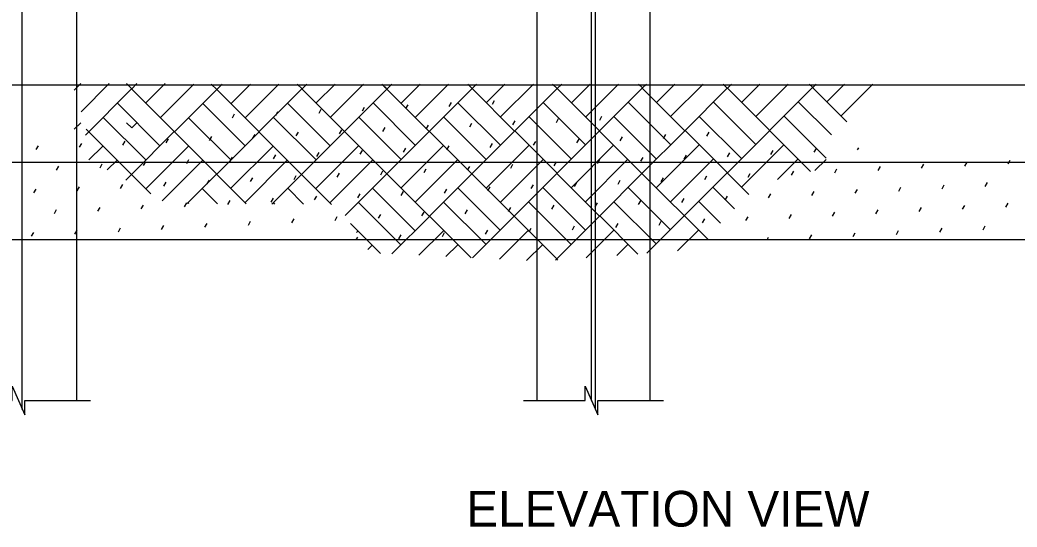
# Model space of a CAD drawing. Extents: x 0 to 61.6, y 0 to 38.9.
# Drawn here: x 19.47 to 30.2, y 12.86 to 18.31 of the extents above; entities that cross this region are included whole.
import ezdxf

# ---------------------------------------------------------------- set-up
doc = ezdxf.new("R2010")
doc.units = 0
for name, color, linetype in [('Dimension', 7, 'Continuous'), ('GroundLines', 7, 'Continuous'), ('Patterning', 7, 'Continuous'), ('SteelMisc', 7, 'Continuous'), ('SteelMisc_h', 7, 'Continuous'), ('Symbols', 7, 'Continuous'), ('TextStructures', 7, 'Continuous'), ('Wood_h', 7, 'Continuous')]:
    doc.layers.add(name, color=color, linetype=linetype)

msp = doc.modelspace()

# ---------------------------------------------------------------- linework, layer by layer
at = {"layer": 'Dimension'}
for p, q in [((23.4, 17.579), (23.409, 17.594)), ((23.621, 17.358), (23.646, 17.4)), ((24.088, 17.382), (24.112, 17.424)), ((24.554, 17.406), (24.576, 17.444)), ((21.756, 17.26), (21.78, 17.302)), ((22.222, 17.285), (22.246, 17.327)), ((22.688, 17.309), (22.713, 17.351)), ((23.155, 17.333), (23.179, 17.375)), ((25.708, 17.234), (25.732, 17.276)), ((23.842, 17.137), (23.867, 17.179)), ((24.309, 17.161), (24.333, 17.203)), ((24.775, 17.185), (24.8, 17.227)), ((25.242, 17.21), (25.266, 17.252)), ((21.977, 17.039), (22.001, 17.081)), ((22.443, 17.064), (22.467, 17.106)), ((22.91, 17.088), (22.934, 17.13)), ((23.376, 17.112), (23.4, 17.154)), ((26.396, 17.037), (26.42, 17.079)), ((26.862, 17.062), (26.886, 17.104)), ((27.329, 17.086), (27.329, 17.086)), ((19.644, 16.917), (19.669, 16.959)), ((20.111, 16.942), (20.135, 16.984)), ((20.577, 16.966), (20.602, 17.008)), ((21.044, 16.991), (21.068, 17.032)), ((21.51, 17.015), (21.535, 17.057)), ((24.063, 16.916), (24.088, 16.958)), ((24.53, 16.94), (24.554, 16.982)), ((24.996, 16.964), (25.021, 17.006)), ((25.463, 16.989), (25.487, 17.031)), ((25.929, 17.013), (25.954, 17.055)), ((22.198, 16.818), (22.222, 16.86)), ((22.664, 16.843), (22.688, 16.885)), ((23.131, 16.867), (23.155, 16.909)), ((23.597, 16.891), (23.621, 16.933)), ((26.617, 16.816), (26.641, 16.858)), ((27.083, 16.841), (27.107, 16.883)), ((27.55, 16.865), (27.574, 16.907)), ((28.016, 16.889), (28.04, 16.931)), ((28.482, 16.914), (28.495, 16.935)), ((19.865, 16.696), (19.89, 16.738)), ((20.332, 16.721), (20.356, 16.763)), ((20.798, 16.745), (20.823, 16.787)), ((21.265, 16.769), (21.289, 16.811)), ((21.731, 16.794), (21.756, 16.836)), ((24.284, 16.695), (24.309, 16.737)), ((24.751, 16.719), (24.775, 16.761)), ((25.217, 16.743), (25.242, 16.785)), ((25.684, 16.768), (25.708, 16.81)), ((26.15, 16.792), (26.175, 16.834)), ((29.17, 16.717), (29.194, 16.759)), ((29.636, 16.741), (29.661, 16.783)), ((30.103, 16.766), (30.124, 16.802)), ((22.419, 16.597), (22.443, 16.639)), ((22.885, 16.622), (22.909, 16.663)), ((23.352, 16.646), (23.376, 16.688)), ((23.818, 16.67), (23.842, 16.712)), ((26.838, 16.595), (26.862, 16.637)), ((27.304, 16.62), (27.328, 16.662)), ((27.771, 16.644), (27.795, 16.686)), ((28.237, 16.668), (28.261, 16.71)), ((28.703, 16.693), (28.728, 16.735)), ((20.553, 16.5), (20.577, 16.542)), ((21.019, 16.524), (21.044, 16.566)), ((21.486, 16.548), (21.51, 16.59)), ((21.952, 16.573), (21.977, 16.615)), ((24.972, 16.498), (24.996, 16.54)), ((25.438, 16.522), (25.463, 16.564)), ((25.905, 16.547), (25.929, 16.589)), ((26.371, 16.571), (26.396, 16.613)), ((29.391, 16.496), (29.415, 16.538)), ((29.857, 16.52), (29.882, 16.562)), ((19.62, 16.451), (19.644, 16.493)), ((20.087, 16.475), (20.111, 16.517)), ((22.64, 16.376), (22.664, 16.418)), ((23.106, 16.4), (23.131, 16.442)), ((23.573, 16.425), (23.597, 16.467)), ((24.039, 16.449), (24.063, 16.491)), ((24.506, 16.474), (24.53, 16.516)), ((27.059, 16.374), (27.083, 16.416)), ((27.525, 16.399), (27.55, 16.441)), ((27.992, 16.423), (28.016, 16.465)), ((28.458, 16.447), (28.482, 16.489)), ((28.925, 16.472), (28.949, 16.514)), ((20.774, 16.279), (20.798, 16.321)), ((21.24, 16.303), (21.265, 16.345)), ((21.707, 16.327), (21.731, 16.369)), ((22.173, 16.352), (22.198, 16.394)), ((25.193, 16.277), (25.217, 16.319)), ((25.659, 16.301), (25.684, 16.343)), ((26.126, 16.326), (26.15, 16.368)), ((26.592, 16.35), (26.617, 16.392)), ((29.612, 16.275), (29.636, 16.317)), ((30.078, 16.299), (30.103, 16.341)), ((19.841, 16.23), (19.865, 16.272)), ((20.308, 16.254), (20.332, 16.296)), ((23.327, 16.179), (23.352, 16.221)), ((23.794, 16.204), (23.818, 16.246)), ((24.26, 16.228), (24.284, 16.27)), ((24.727, 16.253), (24.751, 16.294)), ((27.746, 16.178), (27.771, 16.22)), ((28.213, 16.202), (28.237, 16.244)), ((28.679, 16.226), (28.703, 16.268)), ((29.146, 16.251), (29.17, 16.293)), ((20.995, 16.058), (21.019, 16.1)), ((21.461, 16.082), (21.486, 16.124)), ((21.928, 16.106), (21.952, 16.148)), ((22.394, 16.131), (22.419, 16.173)), ((22.861, 16.155), (22.885, 16.197)), ((25.414, 16.056), (25.438, 16.098)), ((25.88, 16.08), (25.905, 16.122)), ((26.347, 16.105), (26.371, 16.147)), ((26.813, 16.129), (26.838, 16.171)), ((27.28, 16.153), (27.304, 16.195)), ((29.833, 16.054), (29.857, 16.096)), ((19.596, 15.985), (19.62, 16.027)), ((20.062, 16.009), (20.086, 16.051)), ((20.529, 16.033), (20.553, 16.075)), ((23.548, 15.958), (23.573, 16)), ((24.015, 15.983), (24.039, 16.025)), ((24.481, 16.007), (24.505, 16.049)), ((24.948, 16.031), (24.972, 16.073)), ((27.967, 15.957), (27.992, 15.999)), ((28.434, 15.981), (28.458, 16.023)), ((28.9, 16.005), (28.924, 16.047)), ((29.367, 16.03), (29.391, 16.072)), ((22.637, 15.947), (22.64, 15.952)), ((23.089, 15.947), (23.106, 15.976)), ((27.057, 15.947), (27.059, 15.95)), ((27.509, 15.947), (27.525, 15.974))]:
    msp.add_line(p, q, dxfattribs=at)
at = {"layer": 'GroundLines'}
msp.add_line((4.623, 17.613), (45.665, 17.613), dxfattribs=at)
at = {"layer": 'Patterning'}
for p, q in [((20.124, 17.627), (20.055, 17.558)), ((20.124, 17.627), (20.055, 17.558)), ((20.43, 17.627), (20.128, 17.325)), ((20.43, 17.627), (20.128, 17.325)), ((20.673, 17.571), (20.618, 17.627)), ((20.673, 17.571), (20.618, 17.627)), ((20.729, 17.627), (20.673, 17.571)), ((20.729, 17.627), (20.673, 17.571)), ((21.034, 17.627), (20.826, 17.419)), ((21.034, 17.627), (20.826, 17.419)), ((21.034, 17.627), (20.826, 17.419)), ((21.34, 17.622), (20.979, 17.261)), ((21.34, 17.622), (20.979, 17.261)), ((21.34, 17.622), (20.979, 17.261)), ((21.587, 17.564), (21.528, 17.622)), ((21.587, 17.564), (21.528, 17.622)), ((21.587, 17.564), (21.528, 17.622)), ((21.645, 17.622), (21.587, 17.564)), ((21.645, 17.622), (21.587, 17.564)), ((21.645, 17.622), (21.587, 17.564)), ((21.951, 17.622), (21.739, 17.411)), ((21.951, 17.622), (21.739, 17.411)), ((21.951, 17.622), (21.739, 17.411)), ((22.256, 17.622), (21.892, 17.258)), ((22.256, 17.622), (21.892, 17.258)), ((22.256, 17.622), (21.892, 17.258)), ((22.505, 17.572), (22.454, 17.622)), ((22.505, 17.572), (22.454, 17.622)), ((22.505, 17.572), (22.454, 17.622)), ((22.556, 17.622), (22.505, 17.572)), ((22.556, 17.622), (22.505, 17.572)), ((22.556, 17.622), (22.505, 17.572)), ((22.861, 17.622), (22.658, 17.419)), ((22.861, 17.622), (22.658, 17.419)), ((22.861, 17.622), (22.658, 17.419)), ((23.167, 17.622), (22.81, 17.266)), ((23.167, 17.622), (22.81, 17.266)), ((23.167, 17.622), (22.81, 17.266)), ((23.418, 17.569), (23.364, 17.622)), ((23.418, 17.569), (23.364, 17.622)), ((23.418, 17.569), (23.364, 17.622)), ((23.472, 17.622), (23.418, 17.568)), ((23.472, 17.622), (23.418, 17.568)), ((23.472, 17.622), (23.418, 17.568)), ((23.778, 17.622), (23.571, 17.416)), ((23.778, 17.622), (23.571, 17.416)), ((23.778, 17.622), (23.571, 17.416)), ((24.083, 17.622), (23.724, 17.263)), ((24.083, 17.622), (23.724, 17.263)), ((24.083, 17.622), (23.724, 17.263)), ((24.336, 17.576), (24.29, 17.622)), ((24.336, 17.576), (24.29, 17.622)), ((24.336, 17.576), (24.29, 17.622)), ((24.383, 17.622), (24.336, 17.576)), ((24.383, 17.622), (24.336, 17.576)), ((24.383, 17.622), (24.336, 17.576)), ((24.688, 17.622), (24.489, 17.424)), ((24.688, 17.622), (24.489, 17.424)), ((24.688, 17.622), (24.489, 17.424)), ((24.994, 17.622), (24.642, 17.271)), ((24.994, 17.622), (24.642, 17.271)), ((24.994, 17.622), (24.642, 17.271)), ((25.25, 17.573), (25.201, 17.622)), ((25.25, 17.573), (25.201, 17.622)), ((25.25, 17.573), (25.201, 17.622)), ((25.299, 17.622), (25.25, 17.573)), ((25.299, 17.622), (25.25, 17.573)), ((25.299, 17.622), (25.25, 17.573)), ((25.605, 17.622), (25.403, 17.42)), ((25.605, 17.622), (25.403, 17.42)), ((25.605, 17.622), (25.403, 17.42)), ((25.91, 17.622), (25.555, 17.268)), ((25.91, 17.622), (25.555, 17.268)), ((25.91, 17.622), (25.555, 17.268)), ((26.168, 17.581), (26.127, 17.622)), ((26.168, 17.581), (26.127, 17.622)), ((26.168, 17.581), (26.127, 17.622)), ((26.21, 17.622), (26.168, 17.581)), ((26.21, 17.622), (26.168, 17.581)), ((26.21, 17.622), (26.168, 17.581)), ((26.515, 17.622), (26.321, 17.428)), ((26.515, 17.622), (26.321, 17.428)), ((26.515, 17.622), (26.321, 17.428)), ((26.821, 17.622), (26.474, 17.276)), ((26.821, 17.622), (26.474, 17.276)), ((26.821, 17.622), (26.474, 17.276)), ((27.081, 17.578), (27.037, 17.622)), ((27.081, 17.578), (27.037, 17.622)), ((27.081, 17.578), (27.037, 17.622)), ((27.126, 17.622), (27.082, 17.578)), ((27.126, 17.622), (27.082, 17.578)), ((27.126, 17.622), (27.082, 17.578)), ((27.432, 17.622), (27.234, 17.425)), ((27.432, 17.622), (27.234, 17.425)), ((27.432, 17.622), (27.234, 17.425)), ((27.737, 17.622), (27.387, 17.272)), ((27.737, 17.622), (27.387, 17.272)), ((27.737, 17.622), (27.387, 17.272)), ((28, 17.586), (27.963, 17.622)), ((28, 17.586), (27.963, 17.622)), ((28, 17.586), (27.963, 17.622)), ((28.036, 17.622), (28, 17.586)), ((28.036, 17.622), (28, 17.586)), ((28.036, 17.622), (28, 17.586)), ((28.342, 17.622), (28.152, 17.433)), ((28.342, 17.622), (28.152, 17.433)), ((28.342, 17.622), (28.152, 17.433)), ((28.647, 17.622), (28.305, 17.28)), ((28.647, 17.622), (28.305, 17.28)), ((28.647, 17.622), (28.305, 17.28)), ((20.672, 17.57), (20.174, 17.072)), ((20.672, 17.57), (20.174, 17.072)), ((20.672, 17.57), (20.174, 17.072)), ((20.672, 17.57), (21.13, 17.111)), ((20.672, 17.57), (21.13, 17.111)), ((21.587, 17.564), (21.132, 17.109)), ((21.587, 17.564), (21.132, 17.109)), ((21.587, 17.564), (21.132, 17.109)), ((22.503, 17.57), (21.587, 16.653)), ((22.503, 17.57), (21.587, 16.653)), ((22.503, 17.57), (21.587, 16.653)), ((22.5, 16.65), (21.587, 17.564)), ((22.5, 16.65), (21.587, 17.564)), ((22.5, 16.65), (21.587, 17.564)), ((22.503, 17.57), (22.961, 17.112)), ((22.503, 17.57), (22.961, 17.112)), ((22.503, 17.57), (22.961, 17.112)), ((23.418, 17.569), (22.963, 17.113)), ((23.418, 17.569), (22.963, 17.113)), ((23.418, 17.569), (22.963, 17.113)), ((24.335, 17.575), (23.418, 16.658)), ((24.335, 17.575), (23.418, 16.658)), ((24.335, 17.575), (23.418, 16.658)), ((24.332, 16.655), (23.418, 17.568)), ((24.332, 16.655), (23.418, 17.568)), ((24.332, 16.655), (23.418, 17.568)), ((24.335, 17.575), (24.793, 17.116)), ((24.335, 17.575), (24.793, 17.116)), ((24.335, 17.575), (24.793, 17.116)), ((25.25, 17.573), (24.795, 17.118)), ((25.25, 17.573), (24.795, 17.118)), ((25.25, 17.573), (24.795, 17.118)), ((26.166, 17.579), (25.25, 16.663)), ((26.166, 17.579), (25.25, 16.663)), ((26.166, 17.579), (25.25, 16.663)), ((26.163, 16.66), (25.25, 17.573)), ((26.163, 16.66), (25.25, 17.573)), ((26.163, 16.66), (25.25, 17.573)), ((26.166, 17.579), (26.625, 17.121)), ((26.166, 17.579), (26.625, 17.121)), ((26.166, 17.579), (26.625, 17.121)), ((27.081, 17.578), (26.626, 17.123)), ((27.081, 17.578), (26.626, 17.123)), ((27.081, 17.578), (26.626, 17.123)), ((27.998, 17.584), (27.082, 16.668)), ((27.998, 17.584), (27.082, 16.668)), ((27.998, 17.584), (27.082, 16.668)), ((27.977, 16.682), (27.082, 17.578)), ((27.977, 16.682), (27.082, 17.578)), ((27.977, 16.682), (27.082, 17.578)), ((27.998, 17.584), (28.367, 17.215)), ((27.998, 17.584), (28.367, 17.215)), ((27.998, 17.584), (28.367, 17.215)), ((20.519, 17.417), (20.977, 16.959)), ((20.519, 17.417), (20.977, 16.959)), ((21.892, 16.959), (21.437, 17.414)), ((21.892, 16.959), (21.437, 17.414)), ((21.892, 16.959), (21.437, 17.414)), ((22.35, 17.417), (22.809, 16.959)), ((22.35, 17.417), (22.809, 16.959)), ((22.35, 17.417), (22.809, 16.959)), ((23.724, 16.964), (23.269, 17.419)), ((23.724, 16.964), (23.269, 17.419)), ((23.724, 16.964), (23.269, 17.419)), ((24.182, 17.422), (24.64, 16.964)), ((24.182, 17.422), (24.64, 16.964)), ((24.182, 17.422), (24.64, 16.964)), ((25.555, 16.968), (25.1, 17.423)), ((25.555, 16.968), (25.1, 17.423)), ((25.555, 16.968), (25.1, 17.423)), ((26.014, 17.426), (26.472, 16.968)), ((26.014, 17.426), (26.472, 16.968)), ((26.014, 17.426), (26.472, 16.968)), ((27.387, 16.973), (26.932, 17.428)), ((27.387, 16.973), (26.932, 17.428)), ((27.387, 16.973), (26.932, 17.428)), ((27.845, 17.431), (28.201, 17.075)), ((27.845, 17.431), (28.201, 17.075)), ((27.845, 17.431), (28.201, 17.075)), ((25.861, 17.274), (26.319, 16.816)), ((25.861, 17.274), (26.319, 16.816)), ((25.861, 17.274), (26.319, 16.816)), ((27.234, 16.82), (26.779, 17.275)), ((27.234, 16.82), (26.779, 17.275)), ((27.234, 16.82), (26.779, 17.275)), ((27.692, 17.278), (28.145, 16.826)), ((27.692, 17.278), (28.145, 16.826)), ((27.692, 17.278), (28.145, 16.826)), ((20.124, 17.206), (20.055, 17.137)), ((20.366, 17.264), (20.824, 16.806)), ((20.366, 17.264), (20.824, 16.806)), ((20.673, 17.15), (20.618, 17.206)), ((20.729, 17.206), (20.673, 17.15)), ((21.739, 16.806), (21.284, 17.261)), ((21.739, 16.806), (21.284, 17.261)), ((21.739, 16.806), (21.284, 17.261)), ((22.198, 17.264), (22.656, 16.806)), ((22.198, 17.264), (22.656, 16.806)), ((22.198, 17.264), (22.656, 16.806)), ((23.571, 16.811), (23.116, 17.266)), ((23.571, 16.811), (23.116, 17.266)), ((23.571, 16.811), (23.116, 17.266)), ((24.029, 17.269), (24.487, 16.811)), ((24.029, 17.269), (24.487, 16.811)), ((24.029, 17.269), (24.487, 16.811)), ((25.403, 16.816), (24.948, 17.271)), ((25.403, 16.816), (24.948, 17.271)), ((25.403, 16.816), (24.948, 17.271)), ((20.669, 16.65), (20.182, 17.136)), ((20.669, 16.65), (20.182, 17.136)), ((21.13, 17.111), (20.669, 16.65)), ((21.13, 17.111), (20.669, 16.65)), ((21.587, 16.653), (21.132, 17.109)), ((21.587, 16.653), (21.132, 17.109)), ((21.587, 16.653), (21.132, 17.109)), ((22.961, 17.112), (22.5, 16.65)), ((22.961, 17.112), (22.5, 16.65)), ((22.961, 17.112), (22.5, 16.65)), ((23.418, 16.658), (22.963, 17.113)), ((23.418, 16.658), (22.963, 17.113)), ((23.418, 16.658), (22.963, 17.113)), ((24.793, 17.116), (24.332, 16.655)), ((24.793, 17.116), (24.332, 16.655)), ((24.793, 17.116), (24.332, 16.655)), ((25.25, 16.663), (24.795, 17.118)), ((25.25, 16.663), (24.795, 17.118)), ((25.25, 16.663), (24.795, 17.118)), ((26.625, 17.121), (26.163, 16.66)), ((26.625, 17.121), (26.163, 16.66)), ((26.625, 17.121), (26.163, 16.66)), ((27.082, 16.668), (26.626, 17.123)), ((27.082, 16.668), (26.626, 17.123)), ((27.082, 16.668), (26.626, 17.123)), ((20.363, 16.956), (20.213, 16.806)), ((20.363, 16.956), (20.213, 16.806)), ((21.283, 16.954), (20.821, 16.493)), ((21.283, 16.954), (20.821, 16.493)), ((21.283, 16.954), (20.821, 16.493)), ((22.195, 16.956), (21.739, 16.501)), ((22.195, 16.956), (21.739, 16.501)), ((22.195, 16.956), (21.739, 16.501)), ((23.114, 16.959), (22.653, 16.498)), ((23.114, 16.959), (22.653, 16.498)), ((23.114, 16.959), (22.653, 16.498)), ((24.026, 16.961), (23.571, 16.505)), ((24.026, 16.961), (23.571, 16.505)), ((24.026, 16.961), (23.571, 16.505)), ((24.946, 16.963), (24.485, 16.502)), ((24.946, 16.963), (24.485, 16.502)), ((24.946, 16.963), (24.485, 16.502)), ((25.858, 16.965), (25.403, 16.51)), ((25.858, 16.965), (25.403, 16.51)), ((25.858, 16.965), (25.403, 16.51)), ((26.777, 16.968), (26.316, 16.507)), ((26.777, 16.968), (26.316, 16.507)), ((26.777, 16.968), (26.316, 16.507)), ((27.689, 16.97), (27.234, 16.515)), ((27.689, 16.97), (27.234, 16.515)), ((27.689, 16.97), (27.234, 16.515)), ((20.516, 16.803), (20.41, 16.698)), ((20.516, 16.803), (20.41, 16.698)), ((21.435, 16.801), (21.002, 16.368)), ((21.435, 16.801), (21.002, 16.368)), ((21.435, 16.801), (21.002, 16.368)), ((22.347, 16.803), (21.892, 16.348)), ((22.347, 16.803), (21.892, 16.348)), ((22.347, 16.803), (21.892, 16.348)), ((23.267, 16.806), (22.806, 16.345)), ((23.267, 16.806), (22.806, 16.345)), ((23.267, 16.806), (22.806, 16.345)), ((24.179, 16.808), (23.724, 16.353)), ((24.179, 16.808), (23.724, 16.353)), ((24.179, 16.808), (23.724, 16.353)), ((25.099, 16.811), (24.637, 16.349)), ((25.099, 16.811), (24.637, 16.349)), ((25.099, 16.811), (24.637, 16.349)), ((26.011, 16.813), (25.555, 16.357)), ((26.011, 16.813), (25.555, 16.357)), ((26.011, 16.813), (25.555, 16.357)), ((26.93, 16.815), (26.469, 16.354)), ((26.93, 16.815), (26.469, 16.354)), ((26.93, 16.815), (26.469, 16.354)), ((27.842, 16.817), (27.62, 16.595)), ((27.842, 16.817), (27.62, 16.595)), ((27.842, 16.817), (27.62, 16.595)), ((28.143, 16.812), (28.024, 16.693)), ((28.143, 16.812), (28.024, 16.693)), ((28.143, 16.812), (28.024, 16.693)), ((20.669, 16.65), (20.608, 16.589)), ((20.878, 16.441), (20.669, 16.65)), ((21.585, 16.652), (21.27, 16.337)), ((21.585, 16.652), (21.27, 16.337)), ((21.585, 16.652), (21.27, 16.337)), ((21.585, 16.652), (21.903, 16.333)), ((21.585, 16.652), (21.903, 16.333)), ((21.585, 16.652), (21.903, 16.333)), ((22.5, 16.65), (22.182, 16.332)), ((22.5, 16.65), (22.182, 16.332)), ((22.5, 16.65), (22.182, 16.332)), ((22.822, 16.328), (22.5, 16.65)), ((22.822, 16.328), (22.5, 16.65)), ((22.822, 16.328), (22.5, 16.65)), ((23.417, 16.656), (22.97, 16.21)), ((23.417, 16.656), (22.97, 16.21)), ((23.417, 16.656), (22.97, 16.21)), ((23.417, 16.656), (23.875, 16.198)), ((23.417, 16.656), (23.875, 16.198)), ((23.417, 16.656), (23.875, 16.198)), ((24.332, 16.655), (23.877, 16.2)), ((24.332, 16.655), (23.877, 16.2)), ((24.332, 16.655), (23.877, 16.2)), ((25.245, 15.742), (24.332, 16.655)), ((25.245, 15.742), (24.332, 16.655)), ((25.245, 15.742), (24.332, 16.655)), ((25.248, 16.661), (24.339, 15.752)), ((25.248, 16.661), (24.339, 15.752)), ((25.248, 16.661), (24.339, 15.752)), ((25.248, 16.661), (25.706, 16.203)), ((25.248, 16.661), (25.706, 16.203)), ((25.248, 16.661), (25.706, 16.203)), ((26.163, 16.66), (25.708, 16.205)), ((26.163, 16.66), (25.708, 16.205)), ((26.163, 16.66), (25.708, 16.205)), ((26.878, 15.945), (26.163, 16.66)), ((26.878, 15.945), (26.163, 16.66)), ((26.878, 15.945), (26.163, 16.66)), ((27.08, 16.666), (26.216, 15.802)), ((27.08, 16.666), (26.216, 15.802)), ((27.08, 16.666), (26.216, 15.802)), ((27.08, 16.666), (27.313, 16.433)), ((27.08, 16.666), (27.313, 16.433)), ((27.08, 16.666), (27.313, 16.433)), ((21.432, 16.499), (21.596, 16.335)), ((21.432, 16.499), (21.596, 16.335)), ((21.432, 16.499), (21.596, 16.335)), ((22.521, 16.33), (22.351, 16.501)), ((22.521, 16.33), (22.351, 16.501)), ((22.521, 16.33), (22.351, 16.501)), ((23.264, 16.504), (23.722, 16.045)), ((23.264, 16.504), (23.722, 16.045)), ((23.264, 16.504), (23.722, 16.045)), ((24.637, 16.05), (24.182, 16.505)), ((24.637, 16.05), (24.182, 16.505)), ((24.637, 16.05), (24.182, 16.505)), ((25.095, 16.508), (25.554, 16.05)), ((25.095, 16.508), (25.554, 16.05)), ((25.095, 16.508), (25.554, 16.05)), ((26.469, 16.055), (26.014, 16.51)), ((26.469, 16.055), (26.014, 16.51)), ((26.469, 16.055), (26.014, 16.51)), ((26.927, 16.513), (27.16, 16.28)), ((26.927, 16.513), (27.16, 16.28)), ((26.927, 16.513), (27.16, 16.28)), ((21.28, 16.346), (21.289, 16.337)), ((21.28, 16.346), (21.289, 16.337)), ((21.28, 16.346), (21.289, 16.337)), ((22.214, 16.332), (22.198, 16.348)), ((22.214, 16.332), (22.198, 16.348)), ((22.214, 16.332), (22.198, 16.348)), ((23.111, 16.351), (23.569, 15.893)), ((23.111, 16.351), (23.569, 15.893)), ((23.111, 16.351), (23.569, 15.893)), ((24.485, 15.897), (24.029, 16.353)), ((24.485, 15.897), (24.029, 16.353)), ((24.485, 15.897), (24.029, 16.353)), ((24.943, 16.356), (25.401, 15.897)), ((24.943, 16.356), (25.401, 15.897)), ((24.943, 16.356), (25.401, 15.897)), ((26.316, 15.902), (25.861, 16.357)), ((26.316, 15.902), (25.861, 16.357)), ((26.316, 15.902), (25.861, 16.357)), ((26.774, 16.36), (27.008, 16.127)), ((26.774, 16.36), (27.008, 16.127)), ((26.774, 16.36), (27.008, 16.127)), ((24.324, 15.753), (23.877, 16.2)), ((24.324, 15.753), (23.877, 16.2)), ((24.324, 15.753), (23.877, 16.2)), ((25.707, 16.203), (25.245, 15.742)), ((25.707, 16.203), (25.245, 15.742)), ((25.707, 16.203), (25.245, 15.742)), ((26.119, 15.794), (25.708, 16.205)), ((26.119, 15.794), (25.708, 16.205)), ((26.119, 15.794), (25.708, 16.205)), ((23.35, 15.8), (23.027, 16.124)), ((23.35, 15.8), (23.027, 16.124)), ((23.35, 15.8), (23.027, 16.124)), ((23.875, 16.198), (23.471, 15.795)), ((23.875, 16.198), (23.471, 15.795)), ((23.875, 16.198), (23.471, 15.795)), ((23.108, 16.042), (23.091, 16.025)), ((23.108, 16.042), (23.091, 16.025)), ((23.108, 16.042), (23.091, 16.025)), ((24.028, 16.045), (23.763, 15.78)), ((24.028, 16.045), (23.763, 15.78)), ((24.028, 16.045), (23.763, 15.78)), ((24.94, 16.047), (24.63, 15.738)), ((24.94, 16.047), (24.63, 15.738)), ((24.94, 16.047), (24.63, 15.738)), ((25.859, 16.05), (25.561, 15.752)), ((25.859, 16.05), (25.561, 15.752)), ((25.859, 16.05), (25.561, 15.752)), ((26.771, 16.052), (26.546, 15.827)), ((26.771, 16.052), (26.546, 15.827)), ((26.771, 16.052), (26.546, 15.827)), ((23.261, 15.89), (23.212, 15.841)), ((23.261, 15.89), (23.212, 15.841)), ((23.261, 15.89), (23.212, 15.841)), ((24.18, 15.893), (24.054, 15.766)), ((24.18, 15.893), (24.054, 15.766)), ((24.18, 15.893), (24.054, 15.766)), ((25.092, 15.894), (24.922, 15.724)), ((25.092, 15.894), (24.922, 15.724)), ((25.092, 15.894), (24.922, 15.724)), ((26.012, 15.897), (25.892, 15.777)), ((26.012, 15.897), (25.892, 15.777)), ((26.012, 15.897), (25.892, 15.777)), ((25.245, 15.742), (25.231, 15.727)), ((25.245, 15.742), (25.231, 15.727)), ((25.245, 15.742), (25.231, 15.727)), ((25.258, 15.729), (25.245, 15.742)), ((25.258, 15.729), (25.245, 15.742)), ((25.258, 15.729), (25.245, 15.742))]:
    msp.add_line(p, q, dxfattribs=at)
at = {"layer": 'SteelMisc'}
for p, q in [((20.083, 17.613), (20.083, 22.613)), ((25.034, 17.613), (25.034, 22.613)), ((26.25, 17.613), (26.25, 22.613))]:
    msp.add_line(p, q, dxfattribs=at)
at = {"layer": 'SteelMisc_h'}
for p, q in [((19.496, 14.122), (19.496, 22.613)), ((25.621, 14.219), (25.621, 22.613)), ((25.663, 14.122), (25.663, 22.613)), ((20.083, 14.219), (20.083, 17.613)), ((25.034, 14.219), (25.034, 17.613)), ((26.25, 14.219), (26.25, 17.613))]:
    msp.add_line(p, q, dxfattribs=at)
at = {"layer": 'Symbols'}
for points in [[(18.721, 14.219), (19.387, 14.219), (19.387, 14.374), (19.522, 14.064), (19.522, 14.219), (20.228, 14.219)], [(24.888, 14.219), (25.553, 14.219), (25.553, 14.374), (25.688, 14.064), (25.688, 14.219), (26.395, 14.219)]]:
    msp.add_lwpolyline(points, dxfattribs=at)
at = {"layer": 'Wood_h'}
for p, q in [((44.75, 16.78), (6.534, 16.78)), ((44.75, 15.947), (6.534, 15.947))]:
    msp.add_line(p, q, dxfattribs=at)

# ---------------------------------------------------------------- texts
at = {"layer": 'TextStructures'}
msp.add_text('ELEVATION VIEW', height=0.384, dxfattribs=at).set_placement((24.273, 12.862))

doc.saveas('drawing.dxf')
